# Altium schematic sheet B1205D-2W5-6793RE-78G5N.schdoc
size 277 x 190 mm; Device: default297x210; Symbol: default297x210; Name: default297x210; Date: 2025.05.20; Rev: V1.0; Size: "A4"; File: B1205D-2W5-6793RE-78G5N; Sheet: /; @Page No: 1; @Page Count: 1; @Schematic Name: B1205D-2W5-6793RE-78G5N; @Project Name: B1205D-2W5-6793RE-78G5N; @Board Name: B1205D-2W5-6793RE-78G5N; @Update Date: 2025-05-28; @Create Time: 16:02:40; @Update Time: 15:25:28; @Page Name: B1205D-2W5-6793RE-78G5N; @Create Date: 2025-05-22
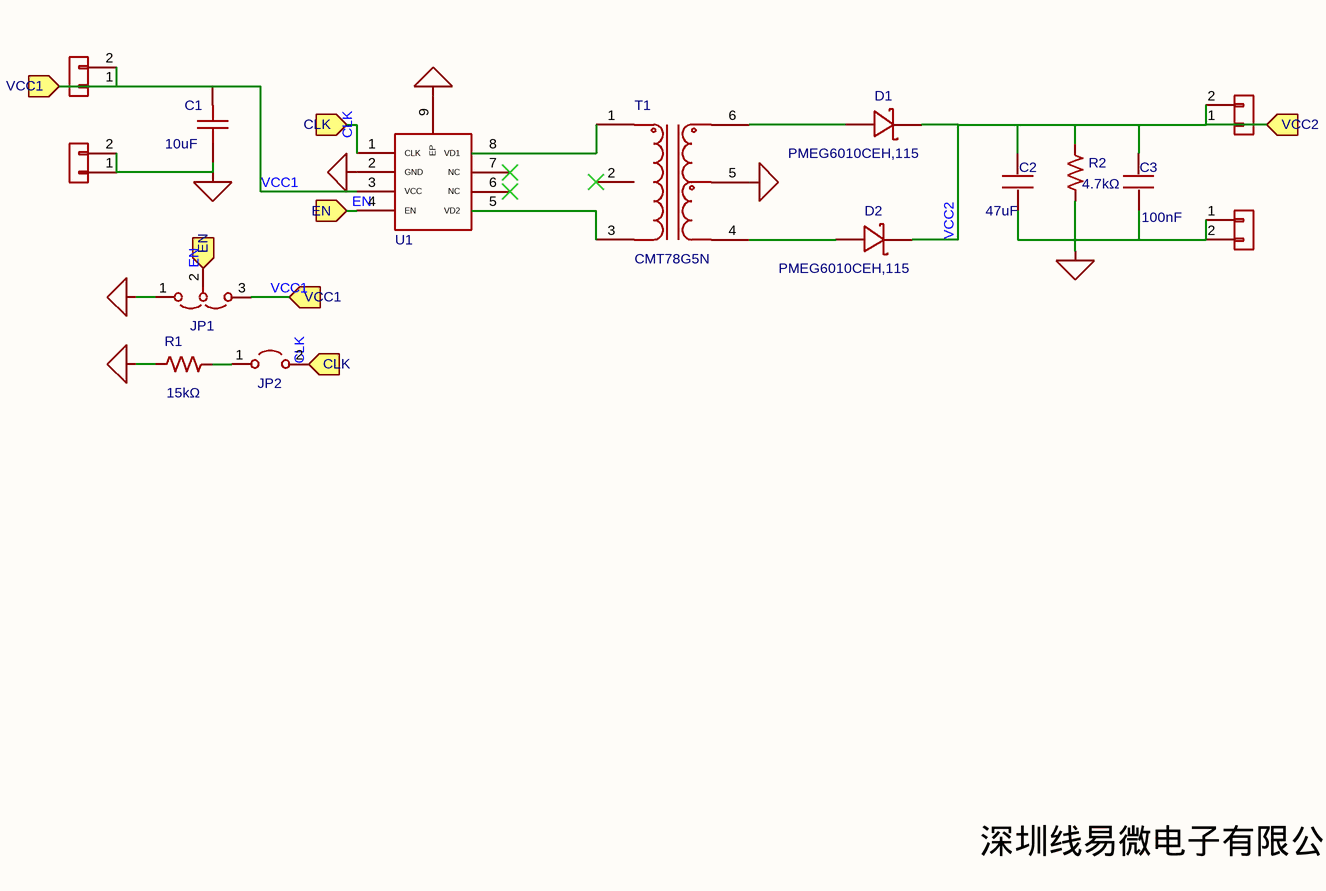
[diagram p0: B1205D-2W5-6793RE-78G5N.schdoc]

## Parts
C1  10uF  [C0603]
C2  47uF  [C0805]
C3  100nF  [C0603]
D1  PMEG6010CEH,115  [SOD-123FL_L2.7-W1.8-LS3.8-RD]
D2  PMEG6010CEH,115  [SOD-123FL_L2.7-W1.8-LS3.8-RD]
J1  Connector_Generic_Conn_01x02  [Connector_PinHeader_2.54mm:PinHeader_1x02_P2.54mm_Vertical]  (value not drawn)
J2  Connector_Generic_Conn_01x02  [Connector_PinHeader_2.54mm:PinHeader_1x02_P2.54mm_Vertical]  (value not drawn)
J3  Connector_Generic_Conn_01x02  [Connector_PinHeader_2.54mm:PinHeader_1x02_P2.54mm_Vertical]  (value not drawn)
J4  Connector_Generic_Conn_01x02  [Connector_PinHeader_2.54mm:PinHeader_1x02_P2.54mm_Vertical]  (value not drawn)
JP1  Jumper_Jumper_3_Open  [Connector_PinHeader_2.54mm:PinHeader_1x03_P2.54mm_Vertical]  (value not drawn)
JP2  Jumper_Jumper_2_Open  [Connector_PinHeader_2.54mm:PinHeader_1x02_P2.54mm_Vertical]  (value not drawn)
R1  15kΩ  [R0603]
R2  4.7kΩ  [R0603]
T1  CMT78G5N  [SMD-6_L9.7-W8.9-P2.54-LS12.8-TL]
U1  (no value)  [ESOP-8_L4.9-W3.9-P1.27-LS6.2-BL-EP]

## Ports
CLK (in), EN (in), VCC1 (in), VCC2 (in)

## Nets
GND1: C1.1 J2.1(Pin_1) J2.2(Pin_2) JP1.1(A) R1.1 U1.2(GND) U1.9(EP)
GND2: C2.1 C3.1 J4.1(Pin_1) J4.2(Pin_2) R2.2 T1.5
CLK: JP2.2(B) U1.1(CLK) ; port CLK
EN: JP1.2(C) U1.4(EN) ; port EN
VCC1: C1.2 J1.1(Pin_1) J1.2(Pin_2) JP1.3(B) U1.3(VCC) ; port VCC1
VCC2: C2.2 C3.2 D1.1(C) D2.1(C) J3.1(Pin_1) J3.2(Pin_2) R2.1 ; port VCC2
NetD1_2: D1.2(A) T1.6
NetD2_2: D2.2(A) T1.4
NetJP2_1: JP2.1(A) R1.2
NetT1_1: T1.1 U1.8(VD1)
NetT1_3: T1.3 U1.5(VD2)

Not connected (* = marked no-connect by the designer): T1 2*; U1 6(NC)* 7(NC)*

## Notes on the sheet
- 深圳线易微电子有限公司

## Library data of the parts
C1 = 0603X106M250NT: 容值:10uF;精度:±20%;额定电压:25V;温度系数:X5R;; Manufacturer: FH(风华); AddInBom: yes; ModelId: ac125912035d415993ca9572d50418b1; ModelName: C0603_L1.6-W0.8-H0.8; ModelTransform: 62.992,31.496,0,0,0,0,0,0,0; Tolerance: ±20%; Voltage Rating: 25V; Temperature Coefficient: X5R
C2 = CC0805MKX5R6BB476: 容值:47uF;精度:±20%;额定电压:10V;温度系数:X5R;; Manufacturer: YAGEO(国巨); Symbol: My_Library_C; AddInBom: yes; ModelId: 1ba041120af144c991958decab20d241; ModelName: C0805_L2.0-W1.3-H1.3; ModelTransform: 78.74,51.181,0,0,0,0,0,0.0005,0; Tolerance: ±20%; Voltage Rating: 10V; Temperature Coefficient: X5R
C3 = CC0603KRX7R9BB104: 容值:100nF;精度:±10%;额定电压:50V;材质(温度系数):X7R;; Manufacturer: YAGEO(国巨); Symbol: My_Library_C; AddInBom: yes; ModelId: ac125912035d415993ca9572d50418b1; ModelName: C0603_L1.6-W0.8-H0.8; ModelTransform: 62.992,31.496,0,0,0,0,0,0,0; Tolerance: ±10%; Voltage Rated: 50V; Temperature Coefficient: X7R
D1 D2 = PMEG6010CEH,115: 正向压降(Vf):660mV@1A;直流反向耐压(Vr):60V;整流电流:1A;; Manufacturer: Nexperia(安世); AddInBom: yes; ModelId: 86f9151e155e4fe2af0c4f2e0a80302e; ModelName: SOD-123FL_L2.8-W1.8-H1.1-LS3.6; ModelTransform: 141.732,70.866,0,180,0,0,0,0,0; Reverse Voltage (Vr): 60V; Rectified Current: 1A; Reverse Leakage Current (Ir): 50uA@60V
J1-J4 = Connector_Generic_Conn_01x02: Users: REF**; sheetfile: EV_CMP6793SE.kicad_sch; AddInBom: yes
JP1 = Jumper_Jumper_3_Open: Users: REF**; sheetfile: EV_CMP6793SE.kicad_sch; AddInBom: yes
JP2 = Jumper_Jumper_2_Open: AddInBom: yes
R1 = RC0603FR-0715KL: 电阻类型:厚膜电阻;阻值:15kΩ;精度:±1%;功率:100mW;最大工作电压:75V;温度系数:±100ppm/℃;; Manufacturer: YAGEO(国巨); Symbol: My_Library_R; AddInBom: yes; ModelId: fc143cca1e79419f9cd78b61e9279f08; ModelTransform: 31.8897,63.7794,0,90,0,0,0,0,0; Tolerance: ±1%; Power(Watts): 100mW; Overload Voltage (Max): 75V
R2 = RC0603FR-074K7L: 电阻类型:厚膜电阻;阻值:4.7kΩ;精度:±1%;功率:100mW;最大工作电压:75V;温度系数:±100ppm/℃;; Manufacturer: YAGEO(国巨); Symbol: My_Library_R; AddInBom: yes; ModelId: fc143cca1e79419f9cd78b61e9279f08; ModelTransform: 31.8897,63.7794,0,90,0,0,0,0,0; Tolerance: ±1%; Power(Watts): 100mW; Overload Voltage (Max): 75V
T1 = CMT78G5N: 电源变压器 SMD-6 隔离耐压：2.5KV 一次绕组：单路 二次绕组：双路 功率5W; Manufacturer: coileasy(线易); AddInBom: yes
U1 = CMP6793RE: AddInBom: yes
